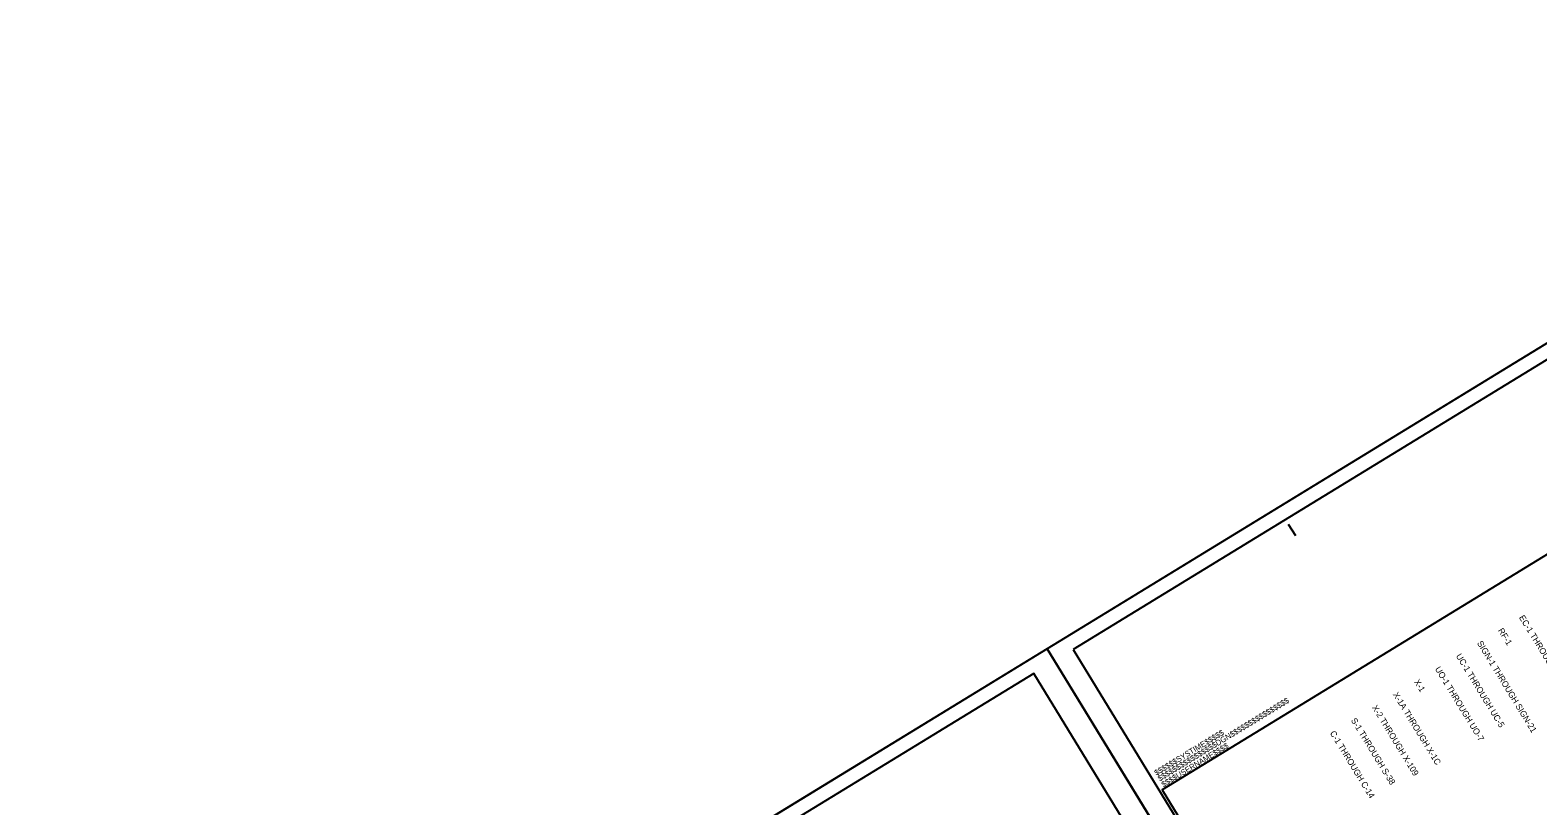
# Model space of a CAD drawing. Extents: x 1750583 to 1791140, y 783580 to 827376.
# Drawn here: x 1750583 to 1765888, y 812289 to 820157 of the extents above; entities that cross this region are included whole.
import ezdxf

# ---------------------------------------------------------------- set-up
doc = ezdxf.new("R2010")
doc.units = 0
for name, color, linetype in [('Prop Dimension Text', 7, 'Continuous'), ('Sheet Cutting Line CELL', 7, 'Continuous'), ('Sheet Plan CELL', 7, 'Continuous'), ('Sheet Plot Border Inside CELL', 7, 'Continuous'), ('Sheet Plot Border Outside CELL', 7, 'Continuous')]:
    doc.layers.add(name, color=color, linetype=linetype)

msp = doc.modelspace()

# ---------------------------------------------------------------- linework, layer by layer
at = {"layer": 'Sheet Cutting Line CELL'}
for p, q in [((1771176, 820157), (1760908, 813883)), ((1760908, 813883), (1750583, 807575)), ((1770557, 798092), (1760908, 813883)), ((1770566, 798076), (1760908, 813883)), ((1760908, 813883), (1770554, 798097))]:
    msp.add_line(p, q, dxfattribs=at)
at = {"layer": 'Sheet Plan CELL'}
for p, q in [((1763355, 815147), (1763427, 815030)), ((1762073, 812451), (1762073, 812451))]:
    msp.add_line(p, q, dxfattribs=at)
msp.add_lwpolyline([(1780514, 804401), (1771919, 818467), (1762073, 812451), (1770667, 798385)], close=True, dxfattribs=at)
at = {"layer": 'Sheet Plot Border Inside CELL'}
for points in [[(1761170, 813876), (1770716, 798253), (1780609, 804298), (1771063, 819921)], [(1750868, 807581), (1760426, 791939), (1770330, 797990), (1760772, 813633)]]:
    msp.add_lwpolyline(points, close=True, dxfattribs=at)
at = {"layer": 'Sheet Plot Border Outside CELL'}
for points in [[(1760908, 813883), (1770554, 798097), (1780822, 804371), (1771176, 820157)], [(1750583, 807575), (1760241, 791768), (1770566, 798076), (1760908, 813883)]]:
    msp.add_lwpolyline(points, close=True, dxfattribs=at)

# ---------------------------------------------------------------- texts
at = {"layer": 'Prop Dimension Text'}
for s, p in [('RF-1', (1765481, 814069)), ('EC-1 THROUGH EC-23', (1765694, 814200)), ('SIGN-1 THROUGH SIGN-21', (1765268, 813939)), ('UC-1 THROUGH UC-5', (1765054, 813809)), ('UO-1 THROUGH UO-7', (1764841, 813678)), ('X-1', (1764628, 813548)), ('X-1A THROUGH X-1C', (1764414, 813418)), ('S-1 THROUGH S-38', (1763988, 813157)), ('X-2 THROUGH X-109', (1764201, 813287)), ('C-1 THROUGH C-14', (1763774, 813027))]:
    msp.add_text(s, height=62.5, rotation=301.4249, dxfattribs=at).set_placement(p)
at = {"layer": 'Sheet Plan CELL'}
for s, p in [('$$$$$$$$$$$$$$$$DGN$$$$$$$$$$$$$$$$', (1762051, 812536)), ('$$$$$$SYSTIME$$$$$', (1762017, 812593)), ('$$$$USERNAME$$$$', (1762089, 812475))]:
    msp.add_text(s, height=57.69, rotation=31.4249, dxfattribs=at).set_placement(p)

doc.saveas('drawing.dxf')
